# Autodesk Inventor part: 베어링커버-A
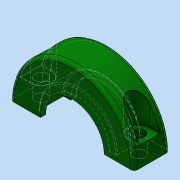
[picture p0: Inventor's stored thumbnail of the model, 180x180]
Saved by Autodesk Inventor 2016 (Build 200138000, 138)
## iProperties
Created: 2018-01
Part Number: 베어링커버-A
Material: 알루미늄 6061
Document SubType Name: Modeling
Designer: mduedu
Density: 2.71 g/cm^3
Appearance: 진녹색
Mass: 7.21302 g
Surface Area: 19.9383 cm^2
Volume: 2.66163 cm^3
Author: mduedu
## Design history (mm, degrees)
sketch "스케치1"
  geometry: L1 (-17.5, 0)-(17.5, 0); A1 r 17.5 centre (0, 0) between (-17.5, 0) and (17.5, 0); 2 further points
  constraints: 2 coincident, 2 end point, 2 point on circle, 1 centre point, 1 horizontal, 1 midpoint
  dimensions: "d0" = 35 diameter of A1
extrude "돌출1" new body sketch "스케치1" stored distance "d1" = 10; taper "d2" = 0 deg
sketch "스케치2"
  geometry: C1 r 11 at (0, 0); C2 r 9 at (0, 0); 1 further point
  constraints: 2 centre point, 2 coincident
  dimensions: "d3" = 22 diameter of C1; "d4" = 18 diameter of C2
extrude "돌출2" cut sketch "스케치2" stored distance "d5" = 7; taper "d6" = 0 deg
extrude "돌출3" cut sketch "스케치2" stored distance "d7" = 7; taper "d8" = 0 deg
fillet "모깎기1" dims "d9" = 0.3
fillet "모깎기2" dims "d10" = 1
node "작업 평면1"
sketch "스케치3"
  geometry: L1 (-15.5, -3.5)-(33.5, -3.5) reference; L2 (-4.771, -6.5)-(-7.771, -6.5); L3 (-7.771, -6.5)-(-7.771, -0.5); L4 (-7.771, -0.5)-(-4.771, -0.5); L5 (-0.46, -7)-(1.517, -7) reference; L6 (1.517, -7)-(1.517, -8.5) reference; L7 (1.517, -8.5)-(-6.724, -8.5) reference; L8 (-7.771, -7.5)-(-7.771, 0.5) reference; L9 (-6.724, 1.5)-(1.517, 1.5) reference; L10 (1.517, 1.5)-(1.517, 0) reference; L11 (1.517, 0)-(-0.46, 0) reference; L12 (-0.798, -0.3)-(-0.798, -6.7) reference; L13 (18.798, -6.7)-(18.798, -0.3) reference; L14 (18.46, 0)-(16.483, 0) reference; L15 (16.483, 0)-(16.483, 1.5) reference; L16 (16.483, 1.5)-(24.724, 1.5) reference; L17 (25.771, 0.5)-(25.771, -7.5) reference; L18 (24.724, -8.5)-(16.483, -8.5) reference; L19 (16.483, -8.5)-(16.483, -7) reference; L20 (16.483, -7)-(18.46, -7) reference; A1 r 3 centre (-4.771, -3.5) between (-4.771, -6.5) and (-4.771, -0.5); 1 further point
  constraints: 6 end point, 2 point on circle, 2 tangent, 1 centre point, 1 collinear, 1 horizontal, 1 parallel, 1 perpendicular, 1 point on line, 8 other
  dimensions: "d12" = 6 distance between parallel lines of L4 L2; "d14" = 6 dimension on A1 L3
extrude "돌출4" cut sketch "스케치3" stored distance "d15" = 0; taper "d16" = 0 deg
sketch "스케치4"
  geometry: 7 further points
  constraints: 4 vertical alignment, 2 horizontal alignment
sketch "스케치5"
  geometry: 2 further points
  constraints: 2 other
hole "구멍1" sketch "스케치5" at (-22.771, 3.5), (4.771, 3.5) diameter "d17" = 3.4; stored, may be unused: countersink angle "d21" = 90 deg, drill point angle "d23" = 0 deg; dims "d18" = 6, "d19" = 4, "d20" = 2, "d22" = 8
fillet "모깎기3" dims "d24" = 0.1
node "솔리드1"
mirror "대칭1"
node "절단 모서리 투영1"
other parameters: "d11" = -5
